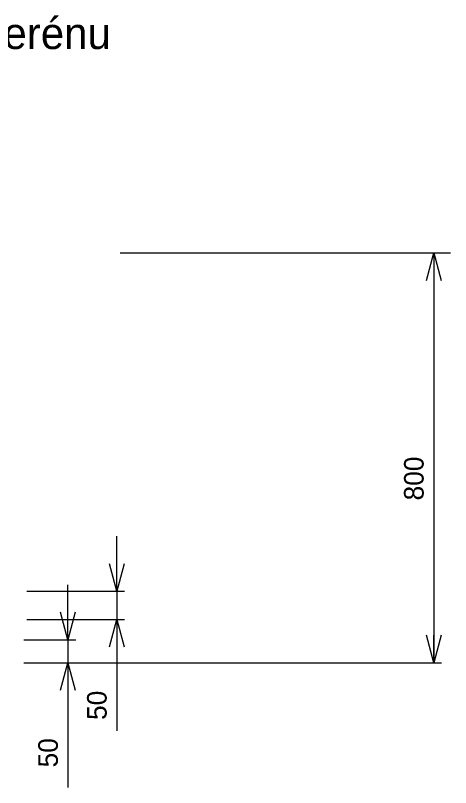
# Model space of a CAD drawing. Extents: x -880561 to -880093, y -1023300 to -1022369.
# Drawn here: x -880498.6 to -880454.3, y -1023243.3 to -1023164.6 of the extents above; entities that cross this region are included whole.
import ezdxf

# ---------------------------------------------------------------- set-up
doc = ezdxf.new("R2010")
doc.units = 0
doc.layers.add('podzemní stavby', color=7, linetype='Continuous')
doc.layers.add('vedeni NN VN', color=7, linetype='Continuous')

# ---------------------------------------------------------------- blocks, each defined once
blk = doc.blocks.new('PEN30')
at = {"layer": 'vedeni NN VN'}
for p, q in [((-1, 0.268), (0, 0)), ((0, 0), (-1, -0.268)), ((0, 0), (-1, 0))]:
    blk.add_line(p, q, dxfattribs=at)

msp = doc.modelspace()

# ---------------------------------------------------------------- linework, layer by layer
at = {"layer": 'podzemní stavby'}
for p, q in [((-880487.957, -1023188.809), (-880454.282, -1023188.809)), ((-880455.997, -1023191.609), (-880455.997, -1023230.559)), ((-880488.314, -1023220.468), (-880488.314, -1023217.668)), ((-880493.292, -1023225.409), (-880493.292, -1023222.609)), ((-880497.492, -1023223.268), (-880487.514, -1023223.268)), ((-880488.314, -1023223.268), (-880488.314, -1023226.138)), ((-880497.492, -1023226.138), (-880487.514, -1023226.138)), ((-880497.781, -1023228.209), (-880492.492, -1023228.209)), ((-880493.292, -1023228.209), (-880493.292, -1023230.559)), ((-880488.314, -1023228.938), (-880488.314, -1023237.487)), ((-880497.781, -1023230.559), (-880492.492, -1023230.559)), ((-880497.581, -1023230.559), (-880455.197, -1023230.559)), ((-880493.292, -1023233.359), (-880493.292, -1023243.272))]:
    msp.add_line(p, q, dxfattribs=at)

# ---------------------------------------------------------------- block references
for p, xscale, yscale, rotation in [((-880455.997, -1023188.809), 2.8000000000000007, 2.8000000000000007, 90.00000000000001), ((-880455.997, -1023188.809), 2.8000000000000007, 2.8000000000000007, 90.00000000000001), ((-880455.997, -1023188.809), 2.8000000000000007, 2.8000000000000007, 90.00000000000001), ((-880488.314, -1023223.268), 2.8000000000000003, 2.8000000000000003, -90.00000000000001), ((-880493.292, -1023228.209), 2.8000000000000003, 2.8000000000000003, -90.00000000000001), ((-880488.314, -1023226.138), 2.8000000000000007, 2.8000000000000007, 90.00000000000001), ((-880455.997, -1023230.559), 2.8000000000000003, 2.8000000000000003, -90.00000000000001), ((-880455.997, -1023230.559), 2.8000000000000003, 2.8000000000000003, -90.00000000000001), ((-880455.997, -1023230.559), 2.8000000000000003, 2.8000000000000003, -90.00000000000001), ((-880493.292, -1023230.559), 2.8000000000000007, 2.8000000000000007, 90.00000000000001)]:
    msp.add_blockref('PEN30', p, dxfattribs=dict(at, xscale=xscale, yscale=yscale, rotation=rotation))

# ---------------------------------------------------------------- texts
msp.add_text('trasa ve volném terénu', height=3.19999, dxfattribs=at).set_placement((-880532.445, -1023168.031))
for s, p in [('800', (-880457.027, -1023214.015)), ('50', (-880489.343, -1023236.383)), ('50', (-880494.319, -1023241.215))]:
    msp.add_text(s, height=2, rotation=90, dxfattribs=at).set_placement(p)

doc.saveas('drawing.dxf')
